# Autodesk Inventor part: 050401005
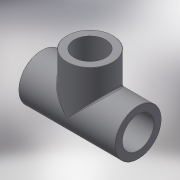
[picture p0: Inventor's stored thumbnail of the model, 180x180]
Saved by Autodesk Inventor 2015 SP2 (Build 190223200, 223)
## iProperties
Created: 2017-10
Part Number: 050401005
Material: Generic
Description: PLASSON THREADED TEE PVC 1/2"
Document SubType Name: Modeling
Designer: KIM
Density: 1 g/cm^3
Appearance: Default
Author: KIM
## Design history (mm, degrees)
derived "050401.ipt"
feature "Solid1::050401.ipt"
feature "Solid2::050401.ipt"
tag "TaggingFeature1"
body "Solid1"
other parameters: "d0" = 55, "d1" = 28, "d2" = 17, "d4" = 18.631, "d5" = 16.7679, "d7" = 0.18631, "d8" = 17, "d9" = 27.5, "d10" = 28, "d15" = 0, "d18" = 18.631, "d24" = 0.18631, "d30" = 18.631, "d31" = 17, "d32" = 0, "d33" = 16.7679, "d35" = 0, "d36" = 0.93155, "G_" = 18.631, "E_" = 28, "H_" = 55, "lt_" = 17
